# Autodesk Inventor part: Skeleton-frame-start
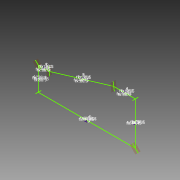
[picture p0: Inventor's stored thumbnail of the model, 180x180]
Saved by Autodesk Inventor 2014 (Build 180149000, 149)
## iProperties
Created: 2009-03
Part Number: Skeleton-frame-start
Document SubType Name: Modeling
Designer: garding
Density: 1 g/cm^3
Material: Generic
Appearance: Default
FrameW: 1.500 in
FrameH: 3.500 in
d20: 3.000 in
d21: 5.000 in
d30: 3.000 in
d31: 5.000 in
d36: 3.000 in
d37: 5.000 in
d42: 3.000 in
d43: 5.000 in
d48: 3.000 in
d49: 5.000 in
d0: 3772.276 mm
d1: 914.400 mm
d2: 1662.856 mm
d3: 81.69 deg
d5: 81.69 deg
d7: 81.69 deg
d8: 81.69 deg
d9: 304.800 mm
d10: 304.800 mm
d12: 38.100 mm
d13: 88.900 mm
d14: 19.050 mm
d15: 44.450 mm
d16: 38.100 mm
d17: 88.900 mm
d18: 19.050 mm
d19: 44.450 mm
d52: 45.00 deg
d53: 45.00 deg
d26: 38.100 mm
d27: 88.900 mm
d28: 19.050 mm
d29: 44.450 mm
d32: 38.100 mm
d33: 88.900 mm
d34: 19.050 mm
d35: 44.450 mm
d38: 38.100 mm
d39: 88.900 mm
d40: 19.050 mm
d41: 44.450 mm
d44: 38.100 mm
d45: 88.900 mm
d46: 19.050 mm
d47: 44.450 mm
Author: garding
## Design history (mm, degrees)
sketch "Sketch1"
  geometry: L1 (0, 0)-(3772.276, 0); L2 (3772.276, 0)-(3772.276, 1662.856); L3 (3772.276, 1662.856)-(2931.388, 1662.856); L4 (2931.388, 1662.856)-(423.63, 914.4); L5 (423.63, 914.4)-(0, 914.4); L6 (0, 914.4)-(0, 0); L7 (401.606, 1065.2)-(445.654, 763.6); L8 (2909.364, 1813.656)-(2953.411, 1512.056); L9 (3880.039, 1770.619)-(3664.513, 1555.093); L10 (3664.513, 107.763)-(3880.039, -107.763); L11 (-107.763, -107.763)-(107.763, 107.763); L12 (107.763, 806.637)-(-107.763, 1022.163); 6 further points
  constraints: 24 end point, 12 midpoint, 4 equal length, 3 parallel, 3 perpendicular, 1 horizontal
  dimensions: "d0" = 3772.27615 distance of L1.start L1.end (derived); "d1" = 914.4 distance of L5.end L1.start (derived); "d2" = 1662.8558 distance of L1.end L2.end (derived); "d3" = 81.691 deg angle of L5 L7 (derived); "d5" = 81.691 deg angle of L4 L7 (= d3); "d7" = 81.691 deg angle of L3 L8 (= d8); "d8" = 81.691 deg angle of L4 L8 (derived); "d9" = 304.8 distance of L8.start L8.end; "d10" = 304.8 distance of L7.start L7.end (= d9); "d52" = 45 deg angle of L6 L12; "d53" = 45 deg angle of L1 L11 (= d52); "d72" = 840.88832 distance of L2.end L3.end (derived)
workplane "Work Plane1"
workplane "Work Plane2"
workplane "Work Plane3"
workplane "Work Plane4"
workplane "Work Plane5"
workplane "Work Plane6"
sketch "Sketch2"
  geometry: L1 (-19.05, -44.45)-(19.05, -44.45); L2 (19.05, -44.45)-(19.05, 44.45); L3 (19.05, 44.45)-(-19.05, 44.45); L4 (-19.05, 44.45)-(-19.05, -44.45); 2 further points
  constraints: 8 end point, 2 parallel, 1 coincident, 1 horizontal, 1 perpendicular
  dimensions: "d12" = 38.1 distance of L1.start L1.end (= FrameW); "d13" = 88.9 distance of L1.end L2.end (= FrameH); "d14" = 19.05 distance from line of L4 point (0, 0) (= 0.5 x d12); "d15" = 44.45 distance from line of L1 point (0, 0) (= 0.5 x d13)
sketch "Sketch3" dims "d0" = 3772.27615 (derived), "d1" = 914.4 (derived), "d2" = 1662.8558 (derived), "d3" = 81.691 deg (derived), "d5" = 81.691 deg (= d3), "d7" = 81.691 deg (= d8), "d8" = 81.691 deg (derived), "d72" = 840.88832 (derived)
  geometry: L1 (-19.05, -44.45)-(19.05, -44.45); L2 (19.05, -44.45)-(19.05, 44.45); L3 (19.05, 44.45)-(-19.05, 44.45); L4 (-19.05, 44.45)-(-19.05, -44.45); 3 further points
  constraints: 8 end point, 2 coincident, 2 parallel, 1 horizontal, 1 perpendicular
  dimensions: "d16" = 38.1 distance of L1.start L1.end (derived); "d17" = 88.9 distance of L1.end L2.end (derived); "d18" = 19.05 distance from line of L4 point (0, 0) (= 0.5 x d16); "d19" = 44.45 distance from line of L1 point (0, 0) (= 0.5 x d17)
sketch "Sketch4"
  geometry: L1 (-19.05, -44.45)-(19.05, -44.45); L2 (19.05, -44.45)-(19.05, 44.45); L3 (19.05, 44.45)-(-19.05, 44.45); L4 (-19.05, 44.45)-(-19.05, -44.45); 4 further points
  constraints: 8 end point, 3 coincident, 2 parallel, 1 horizontal, 1 perpendicular
  dimensions: "d26" = 38.1 distance of L1.start L1.end (derived); "d27" = 88.9 distance of L1.end L2.end (derived); "d28" = 19.05 distance from line of L4 point (0, 0) (= 0.5 x d26); "d29" = 44.45 distance from line of L1 point (0, 0) (= 0.5 x d27)
sketch "Sketch5"
  geometry: L1 (-19.05, -44.45)-(19.05, -44.45); L2 (19.05, -44.45)-(19.05, 44.45); L3 (19.05, 44.45)-(-19.05, 44.45); L4 (-19.05, 44.45)-(-19.05, -44.45); 4 further points
  constraints: 8 end point, 3 coincident, 2 parallel, 1 horizontal, 1 perpendicular
  dimensions: "d32" = 38.1 distance of L1.start L1.end (derived); "d33" = 88.9 distance of L1.end L2.end (derived); "d34" = 19.05 distance from line of L4 point (0, 0) (= 0.5 x d32); "d35" = 44.45 distance from line of L1 point (0, 0) (= 0.5 x d33)
sketch "Sketch6"
  geometry: L1 (-19.05, -44.45)-(19.05, -44.45); L2 (19.05, -44.45)-(19.05, 44.45); L3 (19.05, 44.45)-(-19.05, 44.45); L4 (-19.05, 44.45)-(-19.05, -44.45); 4 further points
  constraints: 8 end point, 3 coincident, 2 parallel, 1 horizontal, 1 perpendicular
  dimensions: "d38" = 38.1 distance of L1.start L1.end (derived); "d39" = 88.9 distance of L1.end L2.end (derived); "d40" = 19.05 distance from line of L4 point (0, 0) (= 0.5 x d38); "d41" = 44.45 distance from line of L1 point (0, 0) (= 0.5 x d39)
sketch "Sketch7"
  geometry: L1 (-19.05, -44.45)-(19.05, -44.45); L2 (19.05, -44.45)-(19.05, 44.45); L3 (19.05, 44.45)-(-19.05, 44.45); L4 (-19.05, 44.45)-(-19.05, -44.45); 7 further points
  constraints: 8 end point, 6 coincident, 2 parallel, 1 horizontal, 1 perpendicular
  dimensions: "d44" = 38.1 distance of L1.start L1.end (derived); "d45" = 88.9 distance of L1.end L2.end (derived); "d46" = 19.05 distance from line of L4 point (0, 0) (= 0.5 x d44); "d47" = 44.45 distance from line of L1 point (0, 0) (= 0.5 x d45)
sketch "Sketch8"
  geometry: L1 (107.763, 806.637)-(-107.763, 1022.163) reference; L2 (-107.763, -107.763)-(107.763, 107.763) reference; L3 (3664.513, 107.763)-(3880.039, -107.763) reference; L4 (3880.039, 1770.619)-(3664.513, 1555.093) reference; L5 (2909.364, 1813.656)-(2953.411, 1512.056) reference; L6 (401.606, 1065.2)-(445.654, 763.6) reference
extrude_surface "ExtrusionSrf13" dims "d73" = 203.2, "d74" = 0
extrude_surface "ExtrusionSrf14" dims "d75" = 203.2, "d76" = 0
extrude_surface "ExtrusionSrf15" dims "d77" = 203.2, "d78" = 0
extrude_surface "ExtrusionSrf16" dims "d79" = 203.2, "d80" = 0
extrude_surface "ExtrusionSrf17" dims "d81" = 203.2, "d82" = 0
extrude_surface "ExtrusionSrf18" dims "d83" = 203.2, "d84" = 0
body "Srf1"
body "Srf2"
body "Srf3"
body "Srf4"
body "Srf5"
body "Srf6"
other parameters: "FrameW" = 38.1 [user parameter; used in 1 equation term], "FrameH" = 88.9 [user parameter; used in 1 equation term], "d20" = 76.2 [user parameter], "d21" = 127 [user parameter], "d30" = 76.2 [user parameter], "d31" = 127 [user parameter], "d36" = 76.2 [user parameter], "d37" = 127 [user parameter], "d42" = 76.2 [user parameter], "d43" = 127 [user parameter], "d48" = 76.2 [user parameter], "d49" = 127 [user parameter]
